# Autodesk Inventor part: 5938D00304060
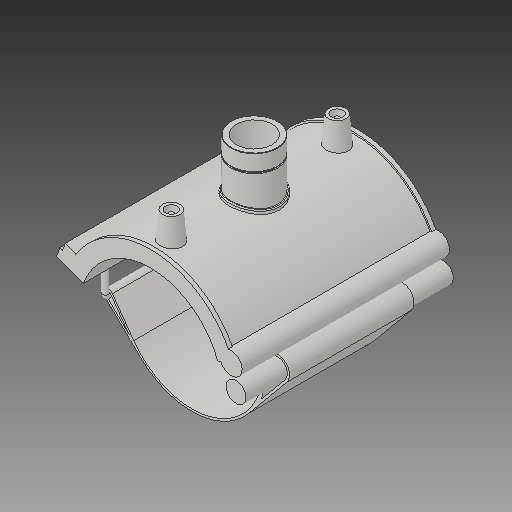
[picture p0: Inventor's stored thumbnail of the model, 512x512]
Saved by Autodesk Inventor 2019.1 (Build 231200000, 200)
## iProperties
Created: 2017-07
Part Number: 5938D00304060
Material: Generic
Description: PLASSON TRANSITION SADDLE 4''DIPS x 1"NPT
Document SubType Name: Modeling
Designer: KIM
Density: 1 g/cm^3
Appearance: Default
Author: KIM
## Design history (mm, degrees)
derived "5938D.ipt"
feature "Solid1::5938D.ipt"
tag "TaggingFeature1"
body "Solid1"
other parameters: "d_" = 121.3, "B_" = 165.1, "H_" = 41.91, "L_" = 176.022, "d_t" = 6, "G_" = 30.291, "d148" = 1.8195, "d160" = 1.8195, "d169" = 1.8195, "d192" = 4.852, "d0" = 121.3, "d1" = 145.56, "d2" = 412.75, "d3" = 30.325, "d4" = 176.022, "d5" = 0, "d40" = 75.6912, "d41" = 42.4074, "d43" = 0, "d45" = 0, "d47" = 114.69, "d48" = 39.3783, "d50" = 0, "d78" = 94.78, "d79" = 15, "d80" = 70.4088, "d82" = 5 deg, "d84" = 4, "d85" = 14, "d86" = 0, "d87" = 3, "d88" = 0, "d96" = 148.4712, "d97" = 3.52044, "d98" = 0, "d102" = 0.90873, "d103" = 30.291, "d104" = 25.146, "d105" = 0, "d106" = 24.2328, "d108" = 0, "d109" = -13.97, "d111" = 0.5, "d112" = 0.5, "d113" = 0, "d114" = 0.5, "d117" = 0.30291, "d120" = 140 deg, "d121" = 24.228, "d122" = 20 deg, "d123" = 582.24, "d124" = 87.336, "d126" = 0, "d143" = 124.939, "d145" = 18.66154, "d149" = 1.8195, "d150" = 20.52769, "d153" = 176.022, "d154" = 0, "d156" = 72.78, "d157" = 160 deg, "d159" = 4.852, "d161" = 1.8195, "d162" = 105.6132, "d163" = 0, "d164" = 60.65, "d167" = 12.13, "d168" = 71.00488, "d170" = 1.8195, "d172" = 0, "d173" = 1, "d175" = 60.65, "d176" = 20 deg, "d177" = 8.491, "d178" = 24.26, "d180" = 0, "d183" = 9.704, "d184" = 6.7928, "d185" = 57.20715, "d186" = 57.20715, "d187" = 72.78, "d188" = 7.278, "d189" = 8.491, "d190" = 0, "d191" = 87.336, "d193" = 4.852, "d194" = 2.48665, "d195" = 90 deg, "d197" = 0, "d199" = 0
